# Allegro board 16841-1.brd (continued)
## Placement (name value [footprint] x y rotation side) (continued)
PG5201  GAP-CLOSE-PWR-3-GP  [GAP-CLOSE-PWR-3]  106.19 8.72 90 bottom
PG5204  GAP-CLOSE-PWR-3-GP  [GAP-CLOSE-PWR-3]  106.95 8.72 90 bottom
PG5206  GAP-CLOSE-PWR-3-GP  [GAP-CLOSE-PWR-3]  107.72 8.72 90 bottom
PG5207  GAP-CLOSE-PWR-3-GP  [GAP-CLOSE-PWR-3]  109.24 8.72 90 bottom
PG5208  GAP-CLOSE-PWR-3-GP  [GAP-CLOSE-PWR-3]  108.48 8.72 90 bottom
PG5209  GAP-CLOSE-PWR-3-GP  [GAP-CLOSE-PWR-3]  110 8.72 90 bottom
PG5210  GAP-CLOSE-PWR-3-GP  [GAP-CLOSE-PWR-3]  124.61 5.42 180 bottom
PG5211  GAP-CLOSE-PWR-3-GP  [GAP-CLOSE-PWR-3]  110.76 8.72 90 bottom
PG5212  GAP-CLOSE-PWR-3-GP  [GAP-CLOSE-PWR-3]  124.61 6.18 180 bottom
PG5213  GAP-CLOSE-PWR-3-GP  [GAP-CLOSE-PWR-3]  75.33 1.99 180 top
PG5214  GAP-CLOSE-PWR-3-GP  [GAP-CLOSE-PWR-3]  124.1 4.41 90 bottom
PG5215  GAP-CLOSE-PWR-3-GP  [GAP-CLOSE-PWR-3]  75.33 2.75 180 top
PG5216  GAP-CLOSE-PWR-3-GP  [GAP-CLOSE-PWR-3]  75.33 3.52 180 top
PG5223  GAP-CLOSE-PWR-3-GP  [GAP-CLOSE-PWR-3]  104.77 8.88 0 bottom
PG5405  GAP-CLOSE-PWR-3-GP  [GAP-CLOSE-PWR-3]  39.9 13.8 90 bottom
PG5406  GAP-CLOSE-PWR-3-GP  [GAP-CLOSE-PWR-3]  38.37 13.8 90 bottom
PG5407  GAP-CLOSE-PWR-3-GP  [GAP-CLOSE-PWR-3]  39.14 13.8 90 bottom
PG5408  GAP-CLOSE-PWR-3-GP  [GAP-CLOSE-PWR-3]  44.6 14.31 90 bottom
PG5409  GAP-CLOSE-PWR-3-GP  [GAP-CLOSE-PWR-3]  45.36 14.31 90 bottom
PG5801  GAP-CLOSE-PWR-3-GP  [GAP-CLOSE-PWR-3]  17.8 54.95 90 bottom
PG5802  GAP-CLOSE-PWR-3-GP  [GAP-CLOSE-PWR-3]  20.98 65.24 0 bottom
PG5803  GAP-CLOSE-PWR-3-GP  [GAP-CLOSE-PWR-3]  17.04 54.95 90 bottom
PG8301  GAP-CLOSE-PWR-3-GP  [GAP-CLOSE-PWR-3]  161.95 125.31 0 bottom
PG8302  GAP-CLOSE-PWR-3-GP  [GAP-CLOSE-PWR-3]  161.95 124.55 0 bottom
PG8303  GAP-CLOSE-PWR-3-GP  [GAP-CLOSE-PWR-3]  161.95 123.79 0 bottom
PG8304  GAP-CLOSE-PWR-3-GP  [GAP-CLOSE-PWR-3]  146.07 122.26 90 bottom
PG8305  GAP-CLOSE-PWR-3-GP  [GAP-CLOSE-PWR-3]  145.31 122.26 90 bottom
PG8306  GAP-CLOSE-PWR-3-GP  [GAP-CLOSE-PWR-3]  144.55 122.26 90 bottom
PG8307  GAP-CLOSE-PWR-3-GP  [GAP-CLOSE-PWR-3]  143.78 122.26 90 bottom
PG8308  GAP-CLOSE-PWR-3-GP  [GAP-CLOSE-PWR-3]  190.27 94.96 90 bottom
PG8309  GAP-CLOSE-PWR-3-GP  [GAP-CLOSE-PWR-3]  190.27 94.96 90 top
PG8310  GAP-CLOSE-PWR-3-GP  [GAP-CLOSE-PWR-3]  191.03 94.96 90 top
PG8311  GAP-CLOSE-PWR-3-GP  [GAP-CLOSE-PWR-3]  191.79 94.96 90 top
PG8312  GAP-CLOSE-PWR-3-GP  [GAP-CLOSE-PWR-3]  192.55 94.96 90 top
PG8313  GAP-CLOSE-PWR-3-GP  [GAP-CLOSE-PWR-3]  189 93.69 180 bottom
PG8314  GAP-CLOSE-PWR-3-GP  [GAP-CLOSE-PWR-3]  196.13 75.78 90 bottom
PG8315  GAP-CLOSE-PWR-3-GP  [GAP-CLOSE-PWR-3]  195.37 75.78 90 bottom
PG8316  GAP-CLOSE-PWR-3-GP  [GAP-CLOSE-PWR-3]  194.61 75.78 90 bottom
PG8317  GAP-CLOSE-PWR-3-GP  [GAP-CLOSE-PWR-3]  193.85 75.78 90 bottom
PG8318  GAP-CLOSE-PWR-3-GP  [GAP-CLOSE-PWR-3]  191.03 94.96 90 bottom
PG8319  GAP-CLOSE-PWR-3-GP  [GAP-CLOSE-PWR-3]  191.79 94.96 90 bottom
PG8320  GAP-CLOSE-PWR-3-GP  [GAP-CLOSE-PWR-3]  192.55 94.96 90 bottom
PL4401  COIL-2D2UH-11-GP  [L11510030H158]  175.79 37.81 180 bottom
PL4501  COIL-1D5UH-43-GP  [L4947-1015H119]  190.27 52.03 180 bottom
PL4502  COIL-1UH-34-GP-U1  [L7066-1830-UH119]  199.41 63.21 0 bottom
PL4701  COIL-D15UH-2-GP  [L7366-1930H158]  154.07 62.42 90 bottom
PL4801  COIL-D15UH-2-GP  [L7366-1930H158]  154.33 40.6 90 bottom
PL4802  COIL-D15UH-2-GP  [L7366-1930H158]  154.33 48.6 90 bottom
PL5001  IND-D47UH-22-GP-U  [L7066-1830-UH119]  154.58 31.71 90 bottom
PL5101  COIL-1UH-73-GP  [L4947-1115H119]  38.25 100.8 90 bottom
PL5201  COIL-1UH-34-GP-U1  [L7066-1830-UH119]  110.52 4.43 90 bottom
PL8201  IND-D36UH-42-GP  [L6965-1530H158]  129.43 100.42 180 bottom
PL8202  IND-D36UH-42-GP  [L6965-1530H158]  138.07 100.42 180 bottom
PL8301  IND-1UH-382-GP  [L2520-D620H48]  149.75 123.66 90 bottom
PL8302  IND-D68UH-40-GP  [L4947-1015H119]  191.79 86.7 0 bottom
PQ4301  DMN5L06K-7-GP  [SOT23DGS2D4H48]  60.22 96.86 0 bottom
PQ4302  MMBT3904-5-GP-U  [SOT23CBE2D4H46-U]  60.85 100.54 0 bottom
PQ4304  LMUN5212T1G-GP  [SOT323CBE2D2H40]  14.12 88.45 180 bottom
PQ4305  LTA024EUB-FS8-GP  [SC70-2D2-312H44]  16.66 88.23 0 bottom
PQ4306  2N7002K-1-GP  [SOT23DGS2D4H44]  44.09 76.8 90 top
PQ4307  2N7002KDW-GP  [SOT-363H44]  39.64 78.7 180 top
PQ4308  2N7002KDW-GP  [SOT-363H44]  33.17 78.19 0 top
PQ4309  2N7002KDW-GP  [SOT-363H44]  36.85 74.76 270 top
PQ4310  2N7002KDW-GP  [SOT-363H44]  40.79 83.02 0 top
PQ4311  2N7002KDW-GP  [SOT-363H44]  36.85 77.81 0 top
PQ4312  2N7002K-1-GP  [SOT23DGS2D4H44]  42.69 80.35 90 top
PQ4313  2N7002KDW-GP  [SOT-363H44]  41.55 75.14 0 top
PQ4314  DMN5L06K-7-GP  [SOT23DGS2D4H48]  53.36 93.43 90 bottom
PQ4402  2N7002K-1-GP  [SOT23DGS2D4H44]  139.72 81.49 180 bottom
PQ4405  2N7002KDW-GP  [SOT-363H44]  193.7 70.19 0 top
PQ4408  MMBT3906-4-GP  [SOT23CBE2D4H44]  193.7 65.37 0 top
PQ4415  2N7002KDW-GP  [SOT-363H44]  208.81 28.15 270 bottom
PQ4416  2N7002KDW-GP  [SOT-363H44]  139.21 78.19 180 bottom
PQ8301  2N7002KDW-GP  [SOT-363H44]  124.48 123.53 270 bottom
PQ8305  2N7002KDW-GP  [SOT-363H44]  124.49 117.94 270 bottom
PQ8306  2N7002KDW-GP  [SOT-363H44]  124.48 115.28 270 bottom
PQ8307  2N7002KDW-GP  [SOT-363H44]  124.48 120.99 270 bottom
PQ8308  2N7002KDW-GP  [SOT-363H44]  203.98 64.35 180 top
PR4302  15KR2F-GP  [R402H16]  57.55 101.81 180 bottom
PR4303  10KR2J-3-GP  [R402H16]  63.01 100.54 180 bottom
PR4304  2K2R2J-2-GP  [R402H16]  55.27 95.46 270 bottom
PR4305  33R2J-2-GP  [R402H16]  62.38 98 0 bottom
PR4306  33R2J-2-GP  [R402H16]  62.38 96.23 0 bottom
PR4307  240KR3-GP  [R603H22]  18.18 88.1 0 top
PR4308  47KR2F-GP  [R402H16]  19.45 86.07 0 top
PR4309  100KR2J-1-GP  [R402H16]  58.31 101.81 0 bottom
PR4310  1KR2J-1-GP  [R402H16]  39.64 74.89 0 top
PR4311  100KR2F-L1-GP  [R402H16]  18.94 79.18 270 top
PR4312  470KR2F-GP  [R402H16]  15.77 86.46 180 bottom
PR4313  84K5R2F-GP  [R402H16]  17.04 86.07 270 bottom
PR4315  18K7R2F-GP  [R402H16]  17.04 79.08 0 top
PR4316  20KR2J-L2-GP  [R402H16]  18.94 79.97 270 top
PR4317  -  [0R0603-PAD]  22.37 96.61 180 top
PR4318  100KR2J-1-GP  [R402H16]  24.79 81.62 180 top
PR4319  200KR2F-L-GP  [R402H16]  41.55 77.05 270 top
PR4320  240KR2F-L-GP  [R402H16]  24.81 78.29 0 top
PR4321  47KR2F-GP  [R402H16]  27.66 77.48 90 top
PR4322  10KR2F-2-GP  [R402H16]  27.71 87.08 0 top
PR4323  100KR2F-L1-GP  [R402H16]  44.72 79.84 180 top
PR4324  100KR2F-L1-GP  [R402H16]  38.88 74.89 180 top
PR4327  10KR2F-2-GP  [R402H16]  31.97 80.22 270 top
PR4328  20KR2F-L-GP  [R402H16]  33.68 80.22 270 top
PR4330  240KR2F-L-GP  [R402H16]  35.45 91.22 90 top
PR4332  100KR2F-L1-GP  [R402H16]  40.15 81.11 270 top
PR4333  10KR2F-2-GP  [R402H16]  24.79 83.4 0 top
PR4335  10KR2J-3-GP  [R402H16]  17.04 81.62 270 bottom
PR4336  680KR2J-GP  [R402H16]  29.05 87.26 90 top
PR4337  240KR2F-L-GP  [R402H16]  35.58 79.84 270 top
PR4338  100R2512J-1-GP  [R2512H28]  35.83 84.29 90 top
PR4339  64K9R2F-1-GP  [R402H16]  35.07 73.37 90 top
PR4340  100KR2F-L1-GP  [R402H16]  34.56 74.64 270 top
PR4341  -  [0R0402-PAD]  34.95 76.16 90 top
PR4342  100KR2F-L1-GP  [R402H16]  35.58 80.61 90 top
PR4343  200KR2F-L-GP  [R402H16]  43.58 73.87 270 top
PR4344  680KR2J-GP  [R402H16]  39.77 72.35 270 top
PR4345  100KR2J-1-GP  [R402H16]  47.9 94.19 0 bottom
PR4346  137KR2F-1-GP  [R402H16]  46.5 92.16 270 bottom
PR4347  100KR2F-L1-GP  [R402H16]  47.39 92.92 270 bottom
PR4401  D02R6F-GP  [R1206H24]  193.19 41.24 90 bottom
PR4402  2D2R3-1-U-GP  [R603H22]  199.16 35.39 180 bottom
PR4403  2D2R5J-1-GP  [R805H24]  205.51 31.84 270 bottom
PR4404  402KR2F-GP  [R402H16]  213.89 28.79 0 bottom
PR4405  4D7R2F-GP  [R402H16]  194.97 32.98 90 bottom
PR4406  100KR2F-L1-GP  [R402H16]  208.17 30.44 0 bottom
PR4407  D01R3721F-GP-U  [R3720H40]  180.49 27.01 90 bottom
PR4408  2D2R3-1-U-GP  [R603H22]  194.71 29.42 270 bottom
PR4409  100KR2F-L1-GP  [R402H16]  200.55 23.46 180 bottom
PR4410  105KR2F-1-GP  [R402H16]  199.03 23.46 0 bottom
PR4411  499R2F-2-GP  [R402H16]  197.51 22.69 180 bottom
PR4412  -  [0R0402-PAD]  196.74 22.69 180 bottom
PR4413  6K04R2F-GP  [R402H16]  195.98 22.69 180 bottom
PR4414  -  [0R0805-PAD]  183.41 43.39 90 top
PR4416  2D2R5J-1-GP  [R805H24]  180.74 40.85 90 top
PR4417  100KR2F-L1-GP  [R402H16]  202.33 29.81 90 top
PR4420  -  [0R0805-PAD]  183.28 31.71 270 top
PR4422  3D3R2F-GP  [R402H16]  202.33 36.28 180 bottom
PR4423  3D3R2F-GP  [R402H16]  201.57 36.28 180 bottom
PR4424  1R2F-L-GP  [R402H16]  194.84 27.01 270 bottom
PR4425  1R2F-L-GP  [R402H16]  194.84 26.25 270 bottom
PR4426  196KR2F-GP  [R402H16]  205.13 26.5 270 bottom
PR4427  100KR2F-L2-GP  [R402H16]  208.81 26.4 270 bottom
PR4429  100KR2F-L2-GP  [R402H16]  205.13 27.27 90 bottom
PR4435  100KR2F-L3-GP  [R402H16]  140.86 76.16 180 bottom
PR4436  1MR2J-1-GP  [R402H16]  193.31 63.33 270 top
PR4450  10KR2F-2-GP  [R402H16]  190.65 71.59 180 top
PR4462  -  [0R0402-PAD]  193.7 67.91 0 top
PR4463  0R2J-2-GP  [R402H16]  194.46 67.91 0 top
PR4472  100KR2F-L3-GP  [R402H16]  140.86 78.07 0 bottom
PR4473  100KR2J-1-GP  [R402H16]  194.71 62.83 180 top
PR4474  100KR2F-L1-GP  [R402H16]  193.95 72.1 270 top
PR4475  680KR2F-GP  [R402H16]  192.37 66.53 270 top
PR4476  -  [0R0402-PAD]  138.58 75.78 0 bottom
PR4477  -  [0R0402-PAD]  187.22 64.6 90 top
PR4478  100R2F-L1-GP-U  [R402H14]  193.06 23.96 90 bottom
PR4501  -  [0R0603-PAD]  186.2 53.94 180 bottom
PR4502  -  [0R0603-PAD]  194.08 66.25 180 bottom
PR4503  0R2J-2-GP  [R402H16]  192.3 60.79 0 top
PR4504  -  [0R0402-PAD]  200.81 70.95 0 top
PR4505  100KR2J-1-GP  [R402H16]  191.79 60.92 180 bottom
PR4506  1KR2F-3-GP  [R402H16]  194.71 56.22 270 bottom
PR4507  1KR2F-3-GP  [R402H16]  200.93 70.95 180 bottom
PR4508  200KR2F-L1-GP  [R402H16]  194.46 60.29 270 bottom
PR4509  1KR2F-3-GP  [R402H16]  194.89 62.85 180 bottom
PR4510  100KR2J-1-GP  [R402H16]  197.81 73.16 0 bottom
PR4511  1KR2F-3-GP  [R402H16]  199.28 72.6 0 top
PR4512  200KR2F-L1-GP  [R402H16]  198.52 72.6 180 top
PR4513  1MR2J-1-GP  [R402H16]  200.05 70.95 180 top
PR4514  1MR2J-1-GP  [R402H16]  192.04 58 270 top
PR4515  -  [0R0402-PAD]  193.19 60.79 180 top
PR4516  -  [0R0402-PAD]  192.04 58.76 90 top
PR4530  0R2J-2-GP  [R402H16]  191.54 60.79 180 top
PR4551  348KR2F-GP  [R402H16]  200.22 73.27 270 bottom
PR4601  0R0402-PAD-1-GP  [0R0402-PAD]  182.27 70.83 270 bottom
PR4602  0R0402-PAD-1-GP  [0R0402-PAD]  182.27 70.06 270 bottom
PR4603  1KR2F-3-GP  [R402H16]  184.55 60.41 90 top
PR4604  100R2F-L3-GP  [R402H16]  184.55 62.7 90 top
PR4605  75R2F-2-GP  [R402H16]  184.55 61.94 90 top
PR4606  45D3R2F-L-GP  [R402H16]  184.55 61.17 90 top
PR4607  100R2F-L3-GP  [R402H16]  184.82 60.43 90 bottom
PR4608  90K9R2F-GP  [R402H16]  180.23 60.54 0 top
PR4609  10KR2F-L1-GP  [R402H15]  184.82 59.67 90 bottom
PR4610  1R2J-GP  [R402H16]  182.27 61.56 180 top
PR4611  NTC-10K-26-GP-U  [NTC-402H22-U]  154.71 35.65 90 bottom
PR4612  0R0402-PAD-1-GP  [0R0402-PAD]  184.42 65.75 270 top
PR4613  0R0402-PAD-1-GP  [0R0402-PAD]  184.04 66 270 bottom
PR4614  0R2J-L-GP  [R402H15]  181 60.54 180 top
PR4615  1KR2F-3-GP  [R402H16]  181.38 65.11 0 top
PR4616  10KR2F-L1-GP  [R402H15]  182.27 58.89 270 bottom
PR4617  NTC-470K-8-GP-U  [NTC-402H22-U]  159.28 43.52 180 bottom
PR4618  11KR2F-L-GP  [R402H16]  182.01 67.02 180 bottom
PR4620  392R2F-GP  [R402H16]  180.11 65.49 270 top
PR4621  27K4R2F-GP  [R402H16]  184.04 58.13 90 bottom
PR4622  10R2F-L1-GP  [R402H16]  184.44 62.72 90 bottom
PR4623  0R0402-PAD-1-GP  [0R0402-PAD]  184.44 61.95 90 bottom
PR4624  49D9R2F-L1-GP  [R402H16]  184.82 61.19 90 bottom
PR4625  2K61R2F-1-GP  [R402H16]  184.04 67.52 270 bottom
PR4626  3K3R2F-2-GP  [R402H16]  182.27 58.13 90 bottom
PR4627  100R2F-L1-GP-U  [R402H14]  181.5 69.18 90 bottom
PR4628  9K31R2F-GP  [R402H16]  184.17 64.48 270 bottom
PR4629  88K7R2F-GP  [R402H16]  184.17 63.71 270 bottom
PR4630  2KR2F-L1-GP  [R402H16]  181.96 56.91 0 bottom
PR4631  100R2F-L1-GP-U  [R402H14]  183.41 53.55 180 bottom
PR4632  301R2F-GP  [R402H16]  178.71 68.79 180 bottom
PR4633  3K01R2F-3-GP  [R402H16]  180.44 56.91 0 bottom
PR4635  1KR2F-3-GP  [R402H16]  171.34 55.08 0 bottom
PR4636  499R2F-2-GP  [R402H16]  181.2 56.91 0 bottom
PR4637  1K69R2F-2-GP  [R402H16]  180.23 68.79 0 bottom
PR4638  2KR2F-L1-GP  [R402H16]  179.47 68.79 180 bottom
PR4639  100R2F-L1-GP-U  [R402H14]  178.2 58.63 90 top
PR4640  2K49R2F-2-L-GP  [R402H16]  176.17 69.18 90 bottom
PR4641  2K61R2F-1-GP  [R402H16]  171.98 51.52 90 bottom
PR4642  324R2F-GP  [R402H16]  176.17 57.36 180 bottom
PR4643  11KR2F-L-GP  [R402H16]  178.07 56.09 90 bottom
PR4644  113KR2F-1-GP  [R402H16]  176.17 66.89 90 bottom
PR4645  1KR2F-L1-GP  [R402H15]  175.41 57.36 180 bottom
PR4646  NTC-10K-26-GP-U  [NTC-402H22-U]  156.61 44.54 270 bottom
PR4647  0R0402-PAD-1-GP  [0R0402-PAD]  176.3 55.08 180 bottom
PR4648  274R2F-GP  [R402H16]  173.01 66.91 90 bottom
PR4649  0R0402-PAD-1-GP  [0R0402-PAD]  169.31 66.25 0 bottom
PR4650  NTC-10K-26-GP-U  [NTC-402H22-U]  154.71 66.51 90 bottom
PR4651  1KR2F-L1-GP  [R402H15]  171.72 67.4 180 bottom
PR4652  11KR2F-L-GP  [R402H16]  171.72 65.62 0 bottom
PR4653  2K61R2F-1-GP  [R402H16]  173.38 64.86 180 bottom
PR4654  NTC-470K-8-GP-U  [NTC-402H22-U]  153.56 53.3 180 bottom
PR4655  27K4R2F-GP  [R402H16]  168.95 58.65 270 bottom
PR4656  2K87R2F-1-GP  [R402H16]  171.74 59.41 90 bottom
PR4657  2KR2F-L1-GP  [R402H16]  171.72 61.05 90 bottom
PR4658  499R2F-2-GP  [R402H16]  171.75 62.57 90 bottom
PR4659  100R2F-L1-GP-U  [R402H14]  171.22 63.84 180 bottom
PR4660  1K91R2F-1-GP  [R402H16]  171.72 61.81 90 bottom
PR4661  86K6R2F-GP  [R402H16]  171.74 57.13 90 bottom
PR4662  10KR2F-L1-GP  [R402H15]  171.74 58.65 90 bottom
PR4663  100R2F-L1-GP-U  [R402H14]  168.8 61.43 0 bottom
PR4665  0R0402-PAD-1-GP  [0R0402-PAD]  180.74 53.43 0 bottom
PR4666  0R0402-PAD-1-GP  [0R0402-PAD]  179.85 53.81 0 bottom
PR4667  0R0402-PAD-1-GP  [0R0402-PAD]  168.04 63.08 180 bottom
PR4668  0R0402-PAD-1-GP  [0R0402-PAD]  169.31 64.22 270 bottom
PR4669  0R2J-L-GP  [R402H15]  174.01 57.87 270 bottom
PR4670  267R2F-1-GP  [R402H16]  176.93 57.36 180 bottom
PR4671  1K54R2F-GP  [R402H16]  179.67 56.91 0 bottom
PR4672  88K7R2F-GP  [R402H16]  179.47 59.07 180 top
PR4701  0R0402-PAD-1-GP  [0R0402-PAD]  168.55 66.25 0 bottom
PR4702  0R0402-PAD-1-GP  [0R0402-PAD]  151.91 55.46 0 bottom
PR4703  2D2R6J-3-GP  [R1206H28]  153.82 59.14 270 top
PR4704  2D2R2F-GP  [R402H16]  151.79 58 180 bottom
PR4705  2D2R3F-L-GP  [R603H24]  154.58 53.4 0 bottom
PR4706  0R0402-PAD-1-GP  [0R0402-PAD]  153.31 58 180 bottom
PR4708  3K65R2F-1-GP  [R402H16]  168.93 64.98 270 bottom
PR4712  5K11R2F-L1-GP  [R402H16]  152.67 55.46 0 bottom
PR4802  0R0402-PAD-1-GP  [0R0402-PAD]  163.22 36.16 270 bottom
PR4803  2D2R2F-GP  [R402H16]  156.74 36.16 180 bottom
PR4804  2D2R3-1-U-GP  [R603H22]  165.76 37.43 90 bottom
PR4805  2D2R6J-3-GP  [R1206H28]  158.01 40.85 90 top
PR4806  0R0402-PAD-1-GP  [0R0402-PAD]  160.68 36.79 270 bottom
PR4808  3K65R2F-1-GP  [R402H16]  171.72 53.05 90 bottom
PR4809  10R2F-L1-GP  [R402H16]  173.5 56.35 270 bottom
PR4810  2D2R3-1-U-GP  [R603H22]  165.5 45.55 90 bottom
PR4811  0R0402-PAD-1-GP  [0R0402-PAD]  162.71 45.17 270 top
PR4812  0R0402-PAD-1-GP  [0R0402-PAD]  159.79 45.17 270 bottom
PR4813  2D2R2F-GP  [R402H16]  159.79 45.17 270 top
PR4814  2D2R6J-3-GP  [R1206H28]  157.88 48.73 90 top
PR4815  10R2F-L1-GP  [R402H16]  174.77 55.21 0 bottom
PR4816  3K65R2F-1-GP  [R402H16]  171.98 52.28 90 bottom
PR4817  5K11R2F-L1-GP  [R402H16]  163.22 36.92 270 bottom
PR4818  5K11R2F-L1-GP  [R402H16]  163.09 45.17 270 bottom
PR4821  100KR2F-L1-GP  [R402H16]  171.85 53.81 90 bottom
PR4822  100KR2F-L1-GP  [R402H16]  172.61 55.59 90 bottom
PR4823  100KR2F-L1-GP  [R402H16]  171.72 56.35 90 bottom
PR4824  100KR2F-L1-GP  [R402H16]  174.26 53.94 90 bottom
PR5001  2D2R3F-L-GP  [R603H24]  171.6 30.19 180 bottom
PR5003  3K65R2F-1-GP  [R402H16]  181.76 67.14 270 top
PR5004  0R0402-PAD-1-GP  [0R0402-PAD]  181.76 66.38 270 top
PR5101  20KR2F-L-GP  [R402H16]  43.2 95.97 180 bottom
PR5102  0R0603-PAD-1-GP-U  [0R0603-PAD-U]  41.93 102.58 270 top
PR5103  0R2J-2-GP  [R402H16]  41.68 98.26 270 top
PR5104  100KR2J-1-GP  [R402H16]  45.49 97.75 90 top
PR5105  1MR2J-1-GP  [R402H16]  45.49 96.1 180 bottom
PR5106  0R2J-2-GP  [R402H16]  43.33 98.77 0 top
PR5107  20KR2F-L-GP  [R402H16]  44.72 96.1 0 bottom
PR5114  -  [0R0402-PAD]  60.85 12.28 90 bottom
PR5118  -  [0R0402-PAD]  60.85 10.76 270 bottom
PR5125  -  [0R0402-PAD]  60.85 14.57 90 bottom
PR5126  0R2J-2-GP  [R402H16]  60.85 15.33 90 bottom
PR5201  88K7R2F-GP  [R402H16]  119.91 7.45 270 top
PR5202  2K55R2F-GP  [R402H16]  118.89 9.61 270 bottom
PR5203  100KR2F-L1-GP  [R402H16]  118.13 7.45 90 top
PR5204  10KR2F-2-GP  [R402H16]  118.89 8.85 90 bottom
PR5208  100KR2J-1-GP  [R402H16]  117.24 8.98 270 top
PR5209  -  [0R0402-PAD]  117.24 9.74 270 top
PR5210  -  [0R0402-PAD]  117.22 9.74 270 bottom
PR5401  47KR2J-2-GP  [R402H16]  36.22 2.63 180 bottom
PR5402  100KR2F-L1-GP  [R402H16]  39.14 3.01 90 bottom
PR5403  16K5R2F-2-GP  [R402H16]  38.88 11.77 90 bottom
PR5404  13K3R2F-L1-GP  [R402H16]  37.1 11.52 90 bottom
PR5406  -  [0R0402-PAD]  36.98 2.63 0 bottom
PR5408  -  [0R0402-PAD]  37.74 3.01 0 bottom
PR5409  47KR2J-2-GP  [R402H16]  42.44 2.63 180 bottom
PR5410  10KR2F-2-GP  [R402H16]  44.6 3.14 90 bottom
PR5417  -  [0R0402-PAD]  44.39 1.89 0 bottom
PR5419  29K4R2F-GP  [R402H16]  44.22 12.28 90 bottom
PR5420  13K7R2F-GP  [R402H16]  43.66 14.69 0 bottom
PR8201  499KR2F-1-GP  [R402H16]  135.4 123.91 180 bottom
PR8202  2D2R2F-GP  [R402H16]  137.38 124.29 90 bottom
PR8203  100KR2J-1-GP  [R402H16]  138.96 120.48 90 bottom
PR8206  20KR2F-L-GP  [R402H16]  134.64 123.91 0 bottom
PR8207  -  [0R0402-PAD]  131.59 123.91 180 bottom
PR8208  2KR2F-3-GP  [R402H16]  133.88 123.91 0 bottom
PR8209  18KR2F-GP  [R402H16]  133.88 123.91 180 top
PR8210  -  [0R0603-PAD]  130.46 118.28 90 bottom
PR8211  -  [0R0603-PAD]  139.47 118.58 270 bottom
PR8212  100R2F-L1-GP-U  [R402H14]  139.47 121.88 0 bottom
PR8213  100R2F-L1-GP-U  [R402H14]  139.47 123.66 0 bottom
PR8215  2D2R5F-2-GP  [R805H24]  134.92 102.98 180 top
PR8216  2D2R5F-2-GP  [R805H24]  133.12 102.98 180 top
PR8220  -  [0R0402-PAD]  140.74 123.15 270 bottom
PR8221  -  [0R0402-PAD]  140.74 122.39 270 bottom
PR8222  20KR2F-L-GP  [R402H16]  133.12 123.91 0 bottom
PR8223  2D2R3J-2-GP  [R603H22]  134.03 116.04 180 top
PR8224  8K45R2F-2-GP  [R402H16]  132.91 115.78 180 bottom
PR8256  1KR2J-1-GP  [R402H16]  128.04 120.1 180 bottom
PR8257  -  [0R0402-PAD]  130.2 122.19 90 top
PR8258  10KR2J-3-GP  [R402H16]  130.2 121.42 90 top
PR8259  10KR2J-3-GP  [R402H16]  130.2 122.96 270 top
PR8260  13KR2F-GP  [R402H16]  126.51 119.47 270 bottom
PR8301  2D2R2F-GP  [R402H16]  157.63 122.64 0 bottom
PR8302  51KR2F-L-GP  [R402H16]  156.1 125.18 90 bottom
PR8303  38K3R2F-GP  [R402H16]  158.14 124.29 90 bottom
PR8304  100KR2F-L1-GP  [R402H16]  153.21 124.75 0 top
PR8306  100R2J-2-GP  [R402H14]  126.77 122.77 90 bottom
PR8307  100KR2J-1-GP  [R402H16]  122.58 123.43 0 bottom
PR8308  -  [0R0402-PAD]  152.55 125.18 270 bottom
PR8309  100R2J-2-GP  [R402H14]  126.77 117.44 90 bottom
PR8310  1KR2J-1-GP  [R402H16]  126.77 124.29 90 bottom
PR8311  100KR2F-L1-GP  [R402H16]  190.9 75.91 0 bottom
PR8313  18KR2F-GP  [R402H16]  159.66 124.17 90 top
PR8315  100KR2J-1-GP  [R402H16]  122.58 117.97 180 bottom
PR8316  100R2J-2-GP  [R402H14]  129.94 119.72 90 bottom
PR8317  100KR2J-1-GP  [R402H16]  122.58 115.28 180 bottom
PR8318  100R2J-2-GP  [R402H14]  126.77 120.23 90 bottom
PR8319  100KR2J-1-GP  [R402H16]  122.58 120.74 180 bottom
PR8320  -  [0R0402-PAD]  153.97 124.75 180 top
PR8321  -  [0R0402-PAD]  191.66 75.91 0 bottom
PR8322  -  [0R0402-PAD]  190.14 75.91 0 bottom
PR8323  0R2J-2-GP  [R402H16]  188.62 75.91 0 bottom
PR8324  -  [0R0603-PAD]  195.85 82.51 0 bottom
PR8325  -  [0R0402-PAD]  188.74 80.35 90 bottom
PR8326  12KR2F-L-GP  [R402H16]  187.47 79.46 90 bottom
PR8327  15KR2F-GP  [R402H16]  187.47 77.94 270 bottom
PR8328  100KR2J-1-GP  [R402H16]  205.89 63.08 90 top
PR8329  100R2J-2-GP  [R402H14]  199.28 74.51 90 top
PR8330  -  [0R0402-PAD]  126.77 120.99 270 bottom
PR8331  -  [0R0402-PAD]  126.77 114.9 270 bottom
PT4402  SE33U25VM-11-GP  [CT7343H83]  184.17 48.6 0 bottom
PT4701  SE330U2VDM-4-GP  [CT7343H83]  147.34 59.02 180 bottom
PT4801  SE330U2VDM-4-GP  [CT7343H83]  147.59 41.87 180 bottom
PT4803  SE330U2VDM-4-GP  [CT7343H83]  147.34 50.89 0 bottom
PT4805  SE33U25VM-11-GP  [CT7343H83]  189.25 65.62 270 bottom
PT8206  SE330U2VDM-4-GP  [CT7343H83]  127.78 93.94 90 bottom
PT8207  SE330U2VDM-4-GP  [CT7343H83]  140.36 87.46 180 bottom
PT8208  SE330U2VDM-4-GP  [CT7343H83]  137.94 93.94 270 bottom
PU4301  AON7403-GP-U  [PPAK-8P-3232H36]  21.99 84.42 180 top
PU4302  AON7403-GP-U  [PPAK-8P-3232H36]  21.36 80.1 90 top
PU4303  AON7403-GP-U  [PPAK-8P-3232H36]  30.07 83.2 180 top
PU4304  AON7403-GP-U  [PPAK-8P-3232H36]  29.61 79.84 270 top
PU4305  SI7625DN-T1-GE3-GP  [PPAK-8P-2H45]  32.53 88.86 90 top
PU4306  SI7625DN-T1-GE3-GP  [PPAK-8P-2H45]  38.37 88.86 270 top
PU4307  SN74AUP1G04DRYR-GP  [XSON6H24]  44.47 50.89 270 top
PU4401  ISL9538HRTZ-GP-U  [QFN32J4-G2D85H34]  200.05 29.55 270 bottom
PU4403  AON7380-GP  [PPAK-8P-3232H36]  183.66 42.63 90 bottom
PU4404  AON7380-GP  [PPAK-8P-3232H36]  182.39 38.82 270 bottom
PU4405  AON7380-GP  [PPAK-8P-3232H36]  183.66 31.2 90 bottom
PU4406  AON7380-GP  [PPAK-8P-3232H36]  182.39 35.01 270 bottom
PU4412  AON7401-GP  [PPAK-8P-3232H36]  173.38 26.38 270 bottom
PU4501  SY8286BRAC-GP  [QFN20Z3-G1D1H36]  191.03 57.24 270 bottom
PU4502  SY8288CRAC-GP  [QFN20Z3-G1D1H36]  196.11 70.19 270 bottom
PU4601  ISL95859AHRTZ-T-GP  [QFN40J5-G3D6-DIFF-H34]  178.71 62.44 0 bottom
PU4701  CSD97396Q4M-GP  [DFN8J4535-G4122-U1H40]  156.36 56.73 180 bottom
PU4801  CSD97396Q4M-GP  [DFN8J4535-G4122-U1H40]  161.06 39.84 270 bottom
PU4802  CSD97396Q4M-GP  [DFN8J4535-G4122-U1H40]  161.06 48.09 270 bottom
PU5001  ISL95808HRZ-T-1-GP  [DFN8G2-G1710-U1H40]  168.93 29.68 90 bottom
PU5002  AON7410-GP  [PPAK-8P-3232H36]  161.44 33.74 90 bottom
PU5003  AON7410-GP  [PPAK-8P-3232H36]  160.17 29.93 270 bottom
PU5101  SY8288RAC-GP  [QFN20Z3-G1H36]  44.34 100.16 180 bottom
PU5102  APL5338XAI-TRG-GP  [MSOP10-G2D5H44]  56.15 12.91 90 bottom
PU5201  AOZ2262QI-10-GP-U  [QFN22G4-G2PH42]  118.13 5.55 180 bottom
PU5401  APL5930KAI-TRG-GP  [SOIC8-G3530H63]  38.63 7.71 0 bottom
PU5403  APL5930KAI-TRG-GP  [SOIC8-G3530H63]  44.09 7.71 0 bottom
PU8201  RT8812AGQW-GP  [QFN20-G1D75H32]  134.78 119.8 270 bottom
PU8202  FDMS3600-02-RJK0215-COLAY-GP  [PPAK-8P-G5324H44-COLAY]  128.8 108.67 90 bottom
PU8204  FDMS3600-02-RJK0215-COLAY-GP  [PPAK-8P-G5324H44-COLAY]  128.8 108.67 270 top
PU8206  FDMS3600-02-RJK0215-COLAY-GP  [PPAK-8P-G5324H44-COLAY]  139.34 108.67 90 top
PU8208  FDMS3600-02-RJK0215-COLAY-GP  [PPAK-8P-G5324H44-COLAY]  139.34 108.67 270 bottom
PU8301  RT8068AZQWID-GP-U  [DFN10G3-G265175H32]  155.21 123.02 270 bottom
PU8302  SY8288RAC-GP  [QFN20Z3-G1H36]  192.3 79.97 90 bottom
PWSW1  SW-TACT-4P-59-GP  [TJE-533-S-V-T-R-744]  138.7 16.98 180 bottom
Q501  DMN5L06K-7-GP  [SOT23DGS2D4H48]  85.92 93.46 0 bottom
Q1701  PJT138KA-GP  [SOT-363H44]  89.81 13.8 90 top
Q1702  2N7002KDW-GP  [SOT-363H44]  87.14 16.22 90 top
Q1801  2N7002KDW-GP  [SOT-363H44]  68.73 15.45 0 top
Q1802  2N7002K-1-GP  [SOT23DGS2D4H44]  75.2 24.34 180 top
Q2001  PJT138KA-GP  [SOT-363H44]  92.5 32.64 180 top
Q2408  2N7002K-1-GP  [SOT23DGS2D4H44]  140.48 17.36 180 top
Q2414  2N7002K-1-GP  [SOT23DGS2D4H44]  141.63 22.19 90 bottom
Q2416  2N7002KDW-GP  [SOT-363H44]  164.49 12.15 270 top
Q2417  2N7002KDW-GP  [SOT-363H44]  142.79 3.59 180 top
Q2505  2N7002K-1-GP  [SOT23DGS2D4H44]  172.74 5.04 270 top
Q2601  2N7002KDW-GP  [SOT-363H44]  56.92 15.96 90 top
Q2602  2N7002K-1-GP  [SOT23DGS2D4H44]  45.11 10.37 90 top
Q2603  MMBT3904-5-GP-U  [SOT23CBE2D4H46-U]  170.71 45.93 270 bottom
Q2701  2N7002K-1-GP  [SOT23DGS2D4H44]  20.09 34 180 top
Q2702  DMP2130L-7-GP  [SOT23DGS2D4H48]  24.91 31.38 270 top
Q3701  2N7002K-1-GP  [SOT23DGS2D4H44]  39.77 29.86 90 top
Q6105  DMN5L06K-7-GP  [SOT23DGS2D4H48]  48.79 6.18 180 bottom
Q6401  RN2418-GP  [SOT23CBE2D6H62]  49.04 9.49 90 bottom
Q6402  RN2418-GP  [SOT23CBE2D6H62]  48.92 2.88 90 bottom
Q6501  PJA3402-R1-00001-GP  [SOT23DGS2D4H44]  92.35 15.58 90 bottom
Q6502  DMP2130L-7-GP  [SOT23DGS2D4H48]  119.65 13.17 180 bottom
Q6503  2N7002K-1-GP  [SOT23DGS2D4H44]  121.43 16.17 90 bottom
Q6504  2N7002KDW-GP  [SOT-363H44]  123.59 18.76 180 bottom
Q6505  RN2418-GP  [SOT23CBE2D6H62]  144.29 25.23 180 bottom
Q7001  2N7002KDW-GP  [SOT-363H44]  214.4 55.71 90 top
Q7301  2N7002K-1-GP  [SOT23DGS2D4H44]  156.74 67.8 0 bottom
Q7601  2N7002KDW-GP  [SOT-363H44]  188.23 69.56 90 top
Q7606  2N7002K-1-GP  [SOT23DGS2D4H44]  187.22 71.97 90 bottom
Q7801  2N7002K-1-GP  [SOT23DGS2D4H44]  190.65 112.99 180 bottom
Q7901  2N7002K-1-GP  [SOT23DGS2D4H44]  144.29 116.17 0 bottom
Q8301  2N7002K-1-GP  [SOT23DGS2D4H44]  120.67 93.43 90 bottom
Q9102  DMP2130L-7-GP  [SOT23DGS2D4H48]  216.17 31.2 180 bottom
Q9104  2N7002K-2-GP  [SOT23DGS2D4H44]  219.73 31.2 180 bottom
R401  1KR2J-1-GP  [R402H16]  136.16 75.78 270 bottom
R402  51R2J-2-GP  [R402H16]  138.32 69.05 180 bottom
R403  499R2F-2-GP  [R402H16]  136.16 75.02 90 bottom
R404  100KR2J-1-GP  [R402H16]  99.97 32.73 90 bottom
R406  51R2J-2-GP  [R402H16]  136.16 70.95 270 bottom
R407  51R2J-2-GP  [R402H16]  125.7 69.3 270 top
R408  51R2J-2-GP  [R402H16]  136.16 67.14 270 bottom
R409  51R2J-2-GP  [R402H16]  136.16 66.38 270 bottom
R410  -  [0R0402-PAD]  98.29 32.73 270 bottom
R412  49D9R2F-GP  [R402H16]  97.81 52.03 270 top
R413  49D9R2F-GP  [R402H16]  97.81 51.27 270 top
R414  49D9R2F-GP  [R402H16]  125.75 73.37 180 top
R415  49D9R2F-GP  [R402H16]  124.99 73.37 180 top
R416  51R2J-2-GP  [R402H16]  136.16 68.67 270 bottom
R417  1KR2J-1-GP  [R402H16]  136.16 67.91 270 bottom
R419  1KR2J-1-GP  [R402H16]  138.45 73.75 90 bottom
R421  51R2J-2-GP  [R402H16]  136.16 69.43 270 bottom
R422  51R2J-2-GP  [R402H16]  136.16 65.62 270 bottom
R423  51R2J-2-GP  [R402H16]  136.16 70.19 270 bottom
R501  121R2F-GP  [R402H16]  97.81 50.51 270 top
R502  80D6R2F-L-GP  [R402H16]  97.81 53.55 270 top
R503  100R2F-L1-GP-U  [R402H14]  97.81 52.79 270 top
R504  -  [0R0402-PAD]  106.57 16.98 180 bottom
R505  470R2F-GP  [R402H16]  104.9 17 0 bottom
R506  220KR2F-GP  [R402H16]  85.41 96 180 bottom
R601  49D9R2F-GP  [R402H16]  126.72 70.06 270 top
R602  -  [0R0402-PAD]  97.81 77.94 270 top
R603  100KR2J-1-GP  [R402H16]  138.45 74.51 270 bottom
R604  1KR2J-1-GP  [R402H16]  124.73 79.84 0 bottom
R605  1KR2J-1-GP  [R402H16]  125.5 79.84 0 bottom
R705  -  [0R0805-PAD]  97.81 55.46 0 top
R709  -  [0R0402-PAD]  138.45 70.7 270 bottom
R719  100R2F-L1-GP-U  [R402H14]  127.5 55.46 0 top
R720  100R2F-L1-GP-U  [R402H14]  126.64 53.43 270 top
R721  100R2F-L1-GP-U  [R402H14]  123.72 77.18 90 top
R722  100R2F-L1-GP-U  [R402H14]  125.62 76.67 0 top
R723  54D9R2F-L1-GP  [R402H16]  138.45 72.22 90 bottom
R726  100R2F-L1-GP-U  [R402H14]  138.45 71.46 90 bottom
R727  56R2J-4-GP  [R402H16]  138.45 72.99 90 bottom
R728  220R2J-L2-GP  [R402H16]  136.16 72.99 90 bottom
R732  -  [0R0402-PAD]  136.16 72.22 270 bottom
R734  100R2F-L1-GP-U  [R402H14]  127.05 46.94 90 top
R735  100R2F-L1-GP-U  [R402H14]  125.6 46.47 0 top
R736  D0002R5J-GP-U  [R805H20]  123.59 59.52 180 top
R738  0R2J-2-GP  [R402H16]  126.13 65.87 0 top
R742  D0002R5J-GP-U  [R805H20]  123.72 63.59 180 top
R743  D0002R5J-GP-U  [R805H20]  115.31 60.16 180 top
R801  24D9R2F-L-GP  [R402H16]  126.26 63.08 180 top
R802  10KR2J-3-GP  [R402H16]  122.45 24.73 180 bottom
R803  100KR2J-1-GP  [R402H16]  125.5 24.73 0 bottom
R804  -  [0R0402-PAD]  124.73 24.73 180 bottom
R1101  -  [0R1206-PAD]  103.78 12.28 270 top
R1102  -  [0R0603-PAD]  123.97 32.85 180 top
R1103  -  [0R0603-PAD]  112.16 35.52 180 top
R1104  -  [0R0603-PAD]  116.71 32.32 270 top
R1204  10KR2F-L1-GP  [R402H15]  65.04 21.55 90 top
R1205  -  [0R0402-PAD]  63.27 21.55 270 top
R1206  2R2F-GP  [R402H16]  70.25 46.95 90 top
R1208  10KR2F-L1-GP  [R402H15]  65.81 20.66 90 top
R1209  24D9R2F-L-GP  [R402H16]  70.25 48.47 90 top
R1210  -  [0R0402-PAD]  64.41 19.39 0 top
R1211  10KR2F-L1-GP  [R402H15]  59.74 43.32 270 top
R1212  -  [0R0402-PAD]  61.46 43.29 90 top
R1215  240R2F-1-GP  [R402H16]  59.84 52.41 270 top
R1216  SC2D2U10V3KX-L-GP  [C603H36]  66.31 17.49 270 top
R1302  10KR2F-L1-GP  [R402H15]  52.01 21.63 90 top
R1303  -  [0R0402-PAD]  50.29 21.63 270 top
R1305  2R2F-GP  [R402H16]  48.53 42.51 270 top
R1306  10KR2F-2-GP  [R402H16]  52.85 22.95 90 top
R1307  0R2J-L-GP  [R402H15]  51.07 22.95 270 top
R1309  24D9R2F-L-GP  [R402H16]  48.53 44.03 270 top
R1310  10KR2F-L1-GP  [R402H15]  45.51 44.49 180 top
R1311  -  [0R0402-PAD]  46.81 44.03 90 top
R1312  240R2F-1-GP  [R402H16]  48.36 53.96 270 top
R1501  100R2F-L1-GP-U  [R402H14]  135.78 40.98 270 bottom
R1502  200R2F-L-GP  [R402H16]  114.07 35.27 90 top
R1503  10KR2J-3-GP  [R402H16]  135.91 36.16 90 bottom
R1603  113R2F-GP  [R402H16]  120.03 37.16 90 top
R1604  100R2F-L1-GP-U  [R402H14]  127.02 37.3 90 top
R1606  10KR2J-3-GP  [R402H16]  123.97 24.73 0 bottom
R1607  10KR2J-3-GP  [R402H16]  113.48 42.71 0 top
R1608  10KR2J-3-GP  [R402H16]  123.21 24.73 0 bottom
R1609  -  [0R0402-PAD]  116.61 35.27 0 top
R1610  -  [0R0402-PAD]  115.84 35.27 0 top
R1701  10KR2J-3-GP  [R402H16]  116.86 38.82 45 top
R1702  1KR2J-1-GP  [R402H16]  89.81 16.47 270 top
R1704  -  [0R0402-PAD]  107.87 14.26 270 bottom
R1706  -  [0R0402-PAD]  107.87 15.03 90 bottom
R1707  10KR2J-3-GP  [R402H16]  73.3 19.39 90 top
R1708  -  [0R0402-PAD]  115.97 20.03 180 bottom
R1711  -  [0R0603-PAD]  73.3 17.49 270 top
R1713  -  [0R0402-PAD]  116.86 21.17 0 bottom
R1714  10KR2J-3-GP  [R402H16]  124.61 82.13 180 bottom
R1715  100KR2J-1-GP  [R402H16]  117.88 19.9 270 bottom
R1716  100KR2F-L1-GP  [R402H16]  122.45 83.78 270 bottom
R1717  10KR2J-3-GP  [R402H16]  138.09 35.37 270 bottom
R1719  47KR2F-GP  [R402H16]  123.72 84.16 0 bottom
R1720  -  [0R0402-PAD]  90.7 15.45 90 top
R1726  10KR2J-3-GP  [R402H16]  89.43 12.15 90 top
R1727  100KR2J-1-GP  [R402H16]  91.21 12.15 90 top
R1728  -  [0R0402-PAD]  92.1 13.8 90 top
R1730  330KR2J-L1-GP  [R402H16]  95.02 32.6 90 top
R1731  20KR2J-L2-GP  [R402H16]  115.89 40.45 270 top
R1737  100KR2J-1-GP  [R402H16]  86.76 14.57 270 top
R1738  10KR2J-3-GP  [R402H16]  115.21 20.03 0 bottom
R1802  1MR2J-1-GP  [R402H16]  136.06 55.71 180 bottom
R1803  2K7R2F-GP  [R402H16]  127.5 57.82 0 top
R1805  15R2F-2-GP  [R402H16]  94 34.76 270 top
R1809  0R2J-2-GP  [R402H16]  135.3 55.71 180 bottom
R1810  0R2J-2-GP  [R402H16]  135.3 53.94 0 bottom
R1811  10R2F-L-GP  [R402H14]  99.97 29.42 270 bottom
R1812  -  [0R0402-PAD]  99.97 28.66 270 bottom
R1813  -  [0R0402-PAD]  97.81 48.98 90 top
R1815  10MR2J-L-GP  [R402H16]  104.67 19.26 180 bottom
R1816  10KR2J-3-GP  [R402H16]  76.6 26.76 180 top
R1818  8K2R2F-1-GP  [R402H16]  114.45 20.03 180 bottom
R1820  10KR2J-3-GP  [R402H16]  97.89 36.13 90 top
R1822  1KR2J-1-GP  [R402H16]  117.24 22.82 90 bottom
R1823  1KR2J-1-GP  [R402H16]  115.46 22.82 90 bottom
R1824  1KR2J-1-GP  [R402H16]  98.34 30.34 180 top
R1825  1KR2J-1-GP  [R402H16]  97.89 32.32 270 top
R1827  15R2F-2-GP  [R402H16]  93.62 41.24 90 top
R1828  15R2F-2-GP  [R402H16]  93.62 42 90 top
R1829  15R2F-2-GP  [R402H16]  93.62 42.76 90 top
R1830  15R2F-2-GP  [R402H16]  93.62 43.52 90 top
R1836  2K2R2J-2-GP  [R402H16]  119.02 22.82 270 bottom
R1837  150KR2J-GP  [R402H16]  95.65 30.95 180 top
R1838  0R2J-2-GP  [R402H16]  99.97 27.9 270 bottom
R1901  200R2F-L-GP  [R402H16]  120.04 37.93 90 top
R1908  -  [0R0402-PAD]  97.81 45.68 90 top
R1909  1KR2J-1-GP  [R402H16]  96.84 48.12 90 top
R1910  1KR2J-1-GP  [R402H16]  96.03 36.92 0 top
R1911  10KR2J-3-GP  [R402H16]  147.21 27.65 90 top
R1912  10KR2J-3-GP  [R402H16]  150.13 28.31 270 top
R1913  10KR2J-3-GP  [R402H16]  97.89 35.37 90 top
R1914  10KR2J-3-GP  [R402H16]  97.89 33.84 90 top
R1915  10KR2J-3-GP  [R402H16]  98.22 35.17 0 bottom
R1916  10KR2J-3-GP  [R402H16]  97.89 34.61 90 top
R1917  10KR2J-3-GP  [R402H16]  98.98 36.64 0 bottom
R1918  10KR2J-3-GP  [R402H16]  100.5 35.11 0 bottom
R1919  10KR2J-3-GP  [R402H16]  97.89 33.08 90 top
R1920  10KR2J-3-GP  [R402H16]  99.74 36.64 0 bottom
R2001  10KR2F-2-GP  [R402H16]  92.48 30.69 90 top
R2002  10KR2J-3-GP  [R402H16]  90.83 33.11 0 top
R2003  -  [0R0402-PAD]  114.32 24.6 0 bottom
R2004  -  [0R0402-PAD]  113.56 24.47 0 bottom
R2007  1KR2J-1-GP  [R402H16]  115.97 17.36 0 bottom
R2009  10KR2J-3-GP  [R402H16]  117.67 29.88 270 bottom
R2010  10KR2J-3-GP  [R402H16]  118.08 28.61 0 bottom
R2019  1KR2J-1-GP  [R402H16]  116.73 17.36 180 bottom
R2020  -  [0R0402-PAD]  120.64 22.33 180 bottom
R2021  -  [0R0402-PAD]  121.51 22.33 180 bottom
R2023  -  [0R0402-PAD]  71.27 100.54 270 top
R2024  -  [0R0402-PAD]  72.94 100.54 90 top
R2025  0R2J-2-GP  [R402H16]  214.52 58.89 180 top
R2026  0R2J-2-GP  [R402H16]  217.93 56.45 180 top
R2027  0R2J-2-GP  [R402H16]  218.33 53.81 90 top
R2028  0R2J-2-GP  [R402H16]  74.7 100.54 90 top
R2029  10KR2J-3-GP  [R402H16]  114.83 29.42 0 bottom
R2030  10KR2J-3-GP  [R402H16]  114.07 29.42 180 bottom
R2031  10KR2J-3-GP  [R402H16]  71.27 101.31 90 top
R2032  10KR2J-3-GP  [R402H16]  72.94 101.31 270 top
R2033  10KR2J-3-GP  [R402H16]  217.34 57.82 270 top
R2034  10KR2J-3-GP  [R402H16]  216.68 55.97 90 top
R2035  10KR2J-3-GP  [R402H16]  219.1 53.05 270 top
R2036  10KR2J-3-GP  [R402H16]  74.32 101.81 0 top
R2037  10KR2J-3-GP  [R402H16]  122.45 32.35 90 top
R2038  10KR2J-3-GP  [R402H16]  121.18 32.45 180 top
R2039  0R2J-2-GP  [R402H16]  75.2 97.24 90 top
R2040  10KR2J-3-GP  [R402H16]  117.75 24.98 0 bottom
R2041  10KR2J-3-GP  [R402H16]  115.21 17.36 0 bottom
R2042  10KR2J-3-GP  [R402H16]  120.06 29.42 0 bottom
R2043  10KR2J-3-GP  [R402H16]  111.7 32.8 180 top
R2044  10KR2J-3-GP  [R402H16]  117.24 28.61 0 bottom
R2045  10KR2J-3-GP  [R402H16]  126.21 18.81 270 top
R2046  10KR2J-3-GP  [R402H16]  221.25 39.84 270 top
R2047  10KR2J-3-GP  [R402H16]  119.27 29.42 0 bottom
R2048  51KR2J-1-GP  [R402H16]  115.59 29.42 0 bottom
R2049  51KR2J-1-GP  [R402H16]  116.35 29.42 0 bottom
R2050  10KR2J-3-GP  [R402H16]  90.83 31.33 0 top
R2051  10KR2J-3-GP  [R402H16]  120.04 35.88 180 top
R2052  10KR2J-3-GP  [R402H16]  120.39 32.45 180 top
R2053  10KR2J-3-GP  [R402H16]  75.08 101.81 0 top
R2101  -  [0R0402-PAD]  116.71 46.42 180 top
R2106  -  [0R0603-PAD]  75.84 22.06 90 top
R2107  -  [0R0603-PAD]  124.99 36.92 90 top
R2108  -  [0R0603-PAD]  123.85 35.65 270 top
R2109  -  [0R0603-PAD]  138.45 38.95 180 bottom
R2110  -  [0R0603-PAD]  123.45 45.68 270 top
R2111  -  [0R0603-PAD]  139.72 38.95 180 bottom
R2201  1MR2J-1-GP  [R402H16]  139.21 29.68 0 bottom
R2202  0R2J-2-GP  [R402H16]  138.45 30.69 0 bottom
R2203  0R2J-2-GP  [R402H16]  138.45 28.92 180 bottom
R2402  -  [0R0402-PAD]  139.72 10.88 270 bottom
R2406  -  [0R0402-PAD]  162.07 25.11 90 top
R2407  100KR2J-1-GP  [R402H16]  162.07 25.87 90 top
R2408  0R2J-2-GP  [R402H16]  162.07 24.34 90 top
R2409  0R2J-2-GP  [R402H16]  154.07 26.38 0 top
R2414  4K7R2J-2-GP  [R402H16]  179.98 5.29 90 top
R2415  10KR2J-3-GP  [R402H16]  159.02 22.95 0 bottom
R2417  100KR2J-1-GP  [R402H16]  140.86 14.82 0 top
R2418  0R2J-2-GP  [R402H16]  139.59 15.33 270 top
R2421  330R2J-3-GP  [R402H16]  148.48 5.68 270 top
R2424  20KR2F-L-GP  [R402H16]  162.96 21.55 180 top
R2426  10KR2J-3-GP  [R402H16]  161.82 18.76 270 top
R2427  0R2J-2-GP  [R402H16]  138.96 20.41 180 top
R2428  -  [0R0402-PAD]  160.8 24.73 180 top
R2429  10KR2J-3-GP  [R402H16]  135.91 35.39 270 bottom
R2430  10KR2J-3-GP  [R402H16]  155.98 25.87 0 top
R2432  1KR2J-1-GP  [R402H16]  160.93 4.91 270 top
R2434  100KR2J-1-GP  [R402H16]  161.82 12.41 270 top
R2435  -  [0R0402-PAD]  140.74 22.31 270 top
R2436  100KR2J-1-GP  [R402H16]  140.23 20.79 90 top
R2437  43R2J-GP  [R402H16]  145.05 3.26 0 top
R2439  0R2J-2-GP  [R402H16]  144.17 25.36 90 top
R2441  100KR2F-L1-GP  [R402H16]  146.45 2.5 90 top
R2442  154KR2F-GP  [R402H16]  146.45 1.74 270 top
R2443  49K9R2F-L-GP  [R402H16]  151.02 4.53 0 top
R2444  100KR2F-L1-GP  [R402H16]  149.12 2.12 180 top
R2445  -  [0R0402-PAD]  148.36 2.12 180 top
R2446  -  [0R0603-PAD]  149.88 16.47 90 bottom
R2447  -  [0R0402-PAD]  161.82 10.88 90 top
R2448  10KR2F-2-GP  [R402H16]  162.2 21.55 180 top
R2449  100KR2J-1-GP  [R402H16]  140.74 21.55 90 top
R2450  100KR2J-1-GP  [R402H16]  148.23 17.61 0 bottom
R2451  100KR2J-1-GP  [R402H16]  160.93 4.15 90 top
R2454  100KR2J-1-GP  [R402H16]  153.97 4.66 0 top
R2458  10KR2J-3-GP  [R402H16]  153.18 26.38 180 top
R2459  -  [0R0402-PAD]  161.82 11.64 90 top
R2461  0R2J-2-GP  [R402H16]  159.53 2.75 180 top
R2462  -  [0R0402-PAD]  149.25 26.38 180 top
R2463  1KR2J-1-GP  [R402H16]  154.73 4.66 0 top
R2464  10KR2J-3-GP  [R402H16]  147.21 26 90 top
R2470  -  [0R0402-PAD]  163.85 15.2 180 top
R2471  0R2J-2-GP  [R402H16]  163.34 19.39 180 top
R2472  -  [0R0402-PAD]  162.2 3.77 0 top
R2473  10KR2J-3-GP  [R402H16]  151.79 7.33 90 bottom
R2475  0R2J-2-GP  [R402H16]  18.94 78.32 90 top
R2477  -  [0R0402-PAD]  161.82 10.12 270 top
R2478  -  [0R0402-PAD]  139.34 12.15 90 top
R2479  0R2J-2-GP  [R402H16]  162.07 23.58 270 top
R2480  100KR2J-1-GP  [R402H16]  179.98 4.53 90 top
R2481  150KR2F-L-GP  [R402H16]  149.5 4.79 90 top
R2482  115KR2F-GP  [R402H16]  150.39 3.26 270 top
R2483  330R2J-3-GP  [R402H16]  148.74 6.18 180 bottom
R2484  100KR2J-1-GP  [R402H16]  157.37 8.98 90 bottom
R2489  100KR2J-1-GP  [R402H16]  139.59 22.19 180 bottom
R2490  -  [0R0402-PAD]  164.1 19.39 180 top
R2494  0R2J-2-GP  [R402H16]  151.15 1.74 270 top
R2496  100KR2J-1-GP  [R402H16]  159.53 4.53 0 top
R2499  0R2J-2-GP  [R402H16]  18.94 77.56 90 top
R2501  4K7R2J-2-GP  [R402H16]  158.39 16.98 90 bottom
R2503  10R2F-L-GP  [R402H14]  171.85 17.11 270 bottom
R2504  10MR2J-L-GP  [R402H16]  170.71 4.91 0 top
R2505  1K6R2F-GP  [R402H16]  175.28 3.26 270 top
R2515  -  [0R0402-PAD]  170.71 12.03 270 bottom
R2517  47KR2F-GP  [R402H16]  175.28 2.5 90 top
R2601  0R2J-2-GP  [R402H16]  45.36 13.04 0 top
R2602  -  [0R0402-PAD]  148.48 14.95 0 bottom
R2603  7K5R2F-1-GP  [R402H16]  54.5 13.55 270 top
R2604  7K5R2F-1-GP  [R402H16]  46.12 13.04 180 top
R2607  10KR2J-3-GP  [R402H16]  149.75 15.33 90 bottom
R2608  27KR2F-L-GP  [R402H16]  141.12 74.76 180 top
R2609  10R2F-L-GP  [R402H14]  141.88 74.76 180 top
R2610  NTC-100K-8-GP  [NTC-603H38]  143.02 76.03 180 top
R2611  -  [0R0402-PAD]  140.99 76.54 0 top
R2612  -  [0R0402-PAD]  205.89 71.97 180 top
R2613  -  [0R0402-PAD]  208.55 72.48 0 top
R2614  -  [0R0402-PAD]  207.79 72.48 0 top
R2615  0R2J-2-GP  [R402H16]  147.72 14.95 0 bottom
R2616  0R2J-2-GP  [R402H16]  45.49 7.71 180 top
R2617  -  [0R0402-PAD]  44.72 7.71 180 top
R2705  -  [0R0603-PAD]  22.96 9.45 0 top
R2707  -  [0R0805-PAD]  24.07 6.44 90 bottom
R2712  -  [0R0805-PAD]  24.07 8.24 90 bottom
R2721  -  [0R0402-PAD]  29.26 17.06 270 top
R2724  -  [0R0603-PAD]  24.53 23.2 0 top
R2726  10KR2J-3-GP  [R402H16]  21.61 30.69 270 top
R2727  20KR2J-L2-GP  [R402H16]  21.48 32.6 90 top
R2729  -  [0R0402-PAD]  18.36 12.84 90 top
R2730  -  [0R0402-PAD]  28.02 20.84 0 top
R2737  -  [0R0402-PAD]  29.74 13.8 270 top
R2738  -  [0R0402-PAD]  29.33 16.19 270 top
R2739  -  [0R0805-PAD]  17.52 22.57 180 top
R2740  -  [0R0402-PAD]  27.26 20.84 0 top
R2741  200KR2F-L-GP  [R402H16]  28.6 12.66 180 bottom
R2742  100KR2J-1-GP  [R402H16]  27.83 14.06 90 bottom
R2743  10KR2J-3-GP  [R402H16]  29.87 13.42 90 bottom
R2744  100KR2J-1-GP  [R402H16]  29.87 12.66 90 bottom
R2745  2K2R2J-2-GP  [R402H16]  13.23 15.45 270 top
R2746  0R2J-2-GP  [R402H16]  29.74 19.52 270 top
R2747  100KR2J-1-GP  [R402H16]  22.22 9.71 0 bottom
R2748  0R3J-0-U-GP  [R603H22]  33.29 14.77 270 top
R2749  -  [0R0603-PAD]  33.29 16.06 90 top
R2750  0R3J-0-U-GP  [R603H22]  19.2 22.44 180 bottom
R2751  -  [0R0603-PAD]  20.52 22.74 0 bottom
R2752  -  [0R0402-PAD]  29.74 20.28 270 top
R2753  -  [0R0402-PAD]  18.36 14.39 90 top
R2754  0R2J-2-GP  [R402H16]  18.36 13.63 90 top
R2905  -  [0R0402-PAD]  14.42 13.09 90 bottom
R2906  -  [0R0603-PAD]  19.07 13.5 0 bottom
R2907  -  [0R0603-PAD]  18.08 17.92 90 top
R2908  10R2F-L-GP  [R402H14]  16.41 12.91 180 bottom
R2909  -  [0R0603-PAD]  18.08 19.19 90 top
R2910  10R2F-L-GP  [R402H14]  14.96 8.98 315 bottom
R2911  -  [0R0603-PAD]  17.8 15.45 0 bottom
R2912  -  [0R0402-PAD]  35.07 3.77 270 top
R2913  -  [0R0402-PAD]  35.58 5.55 0 top
R2914  -  [0R0402-PAD]  30.25 10.63 0 top
R2915  -  [0R0402-PAD]  32.66 9.49 0 top
R2921  -  [0R0402-PAD]  14.45 11.9 90 bottom
R2922  -  [0R0402-PAD]  15.51 16.09 90 top
R2923  -  [0R0603-PAD]  11.53 14.39 90 top
R3401  -  [0R0402-PAD]  17.29 42.12 270 bottom
R3402  -  [0R0402-PAD]  17.17 46.19 270 bottom
R3403  20KR2F-L-GP  [R402H16]  21.36 42.89 90 top
R3404  22K1R2F-L-GP  [R402H16]  21.36 42.12 90 top
R3405  -  [0R0402-PAD]  17.29 40.98 270 bottom
R3406  -  [0R0402-PAD]  17.29 44.28 270 bottom
R3501  100KR2J-1-GP  [R402H16]  14.75 39.2 90 bottom
R3605  -  [0R0402-PAD]  20.09 50.51 270 top
R3606  -  [0R0402-PAD]  20.09 51.27 270 top
R3609  -  [0R0402-PAD]  20.09 48.98 270 top
R3610  -  [0R0402-PAD]  20.09 49.74 270 top
R3611  -  [0R0402-PAD]  22.73 27.62 270 top
R3612  -  [0R0402-PAD]  22.75 25.51 270 top
R3613  -  [0R0402-PAD]  22.75 26.28 270 top
R3614  -  [0R0402-PAD]  22.73 28.38 270 top
R3706  1MR2J-1-GP  [R402H16]  29.48 25.61 90 top
R3707  2K2R2J-2-GP  [R402H16]  29.48 28.66 90 top
R3708  30KR2J-4-GP  [R402H16]  33.8 23.07 180 top
R3709  10KR2F-2-GP  [R402H16]  34.56 23.33 0 top
R3724  4K7R2J-2-GP  [R402H16]  29.48 32.47 90 top
R3725  10KR2F-2-GP  [R402H16]  28.21 26.76 0 top
R3726  10KR2F-2-GP  [R402H16]  29.48 30.95 90 top
R3727  -  [0R0402-PAD]  35.07 34.38 180 top
R3728  -  [0R0402-PAD]  33.04 34.38 180 top
R3729  -  [0R0402-PAD]  29.48 26.38 270 top
R3730  100KR2F-L1-GP  [R402H16]  29.48 31.71 90 top
R3731  -  [0R0402-PAD]  29.48 29.42 90 top
R3732  -  [0R0603-PAD]  39.01 22.44 270 top
R3733  -  [0R0402-PAD]  40.66 23.2 180 top
R3734  100KR2F-L1-GP  [R402H16]  29.1 34.5 0 top
R3735  2MR2-GP  [R402H16]  30.88 25.61 0 top
R3736  -  [0R0603-PAD]  34.06 34.63 0 top
R3738  10KR2J-3-GP  [R402H16]  41.8 29.93 0 top
R3739  909KR2F-GP  [R402H16]  37.43 34.3 180 top
R3740  301KR2F-1-GP  [R402H16]  38.63 36.16 90 top
R3741  30KR2F-GP  [R402H16]  35.33 22.95 0 top
R3742  10KR2F-L1-GP  [R402H15]  36.09 22.95 180 top
R3801  10KR2J-L-GP  [R402H15]  36.22 63.21 90 top
R3802  10KR2J-L-GP  [R402H15]  37.99 63.21 270 top
R3812  -  [0R0603-PAD]  32.15 48.86 180 top
R3814  -  [0R0402-PAD]  40.79 61.68 270 top
R3816  -  [0R0402-PAD]  40.79 62.44 270 top
R3818  10KR2J-3-GP  [R402H16]  32.79 60.16 90 top
R3821  4K7R2J-2-GP  [R402H16]  32.79 58.76 90 top
R3830  2MR2F-GP  [R402H16]  16.15 99.53 90 top
R3831  2MR2F-GP  [R402H16]  16.15 100.29 90 top
R3832  -  [0R0402-PAD]  9.67 90.77 0 bottom
R3833  -  [0R0402-PAD]  10.43 90.77 0 bottom
R3834  -  [0R0402-PAD]  14.12 88.1 180 top
R3835  -  [0R0402-PAD]  14.88 88.1 180 top
R3836  -  [0R0402-PAD]  12.34 90.77 0 bottom
R3837  -  [0R0402-PAD]  11.58 90.77 0 bottom
R3838  -  [0R0402-PAD]  16.66 88.48 180 top
R3839  -  [0R0402-PAD]  15.9 88.48 180 top
R3840  1KR2J-1-GP  [R402H16]  33.04 56.48 90 top
R3841  1KR2J-1-GP  [R402H16]  32.91 57.24 270 top
R3842  1KR2J-1-GP  [R402H16]  32.79 54.32 90 top
R3843  1KR2J-1-GP  [R402H16]  33.17 55.08 270 top
R3844  20KR2J-L3-GP  [R402H16]  34.44 50.38 0 top
R3845  1KR2J-1-GP  [R402H16]  42.18 52.54 180 top
R3846  1KR2J-1-GP  [R402H16]  41.42 52.54 0 top
R3847  1KR2J-1-GP  [R402H16]  32.91 51.14 180 top
R3849  -  [0R0402-PAD]  39.77 63.71 270 top
R3852  1KR2J-1-GP  [R402H16]  35.2 50.38 180 top
R3853  -  [0R0402-PAD]  37.61 40.85 270 top
R3854  -  [0R0402-PAD]  35.07 39.97 90 top
R3855  -  [0R0402-PAD]  34.06 46.7 0 top
R3856  -  [0R0402-PAD]  35.58 46.7 0 top
R3857  -  [0R0402-PAD]  33.29 46.7 0 top
R3858  -  [0R0402-PAD]  36.34 46.7 0 top
R3859  -  [0R0402-PAD]  29.99 44.92 180 top
R3860  -  [0R0402-PAD]  39.39 44.28 90 top
R3861  0R2J-2-GP  [R402H16]  11.58 91.27 270 top
R3862  0R2J-2-GP  [R402H16]  11.58 92.04 270 top
R3863  0R2J-2-GP  [R402H16]  11.58 93.69 270 top
R3864  0R2J-2-GP  [R402H16]  11.58 92.92 270 top
R3870  1KR2J-1-GP  [R402H16]  33.68 51.14 0 top
R3871  1KR2J-1-GP  [R402H16]  42.44 56.09 270 top
R3872  1KR2J-1-GP  [R402H16]  45.99 56.35 180 top
R3873  1KR2J-1-GP  [R402H16]  45.08 58.71 0 top
R3874  1KR2J-1-GP  [R402H16]  42.84 59.52 270 top
R4002  -  [0R0402-PAD]  155.21 19.39 180 bottom
R4003  10KR2J-3-GP  [R402H16]  81.78 6.34 180 top
R4005  1KR2J-1-GP  [R402H16]  150.64 22.57 270 bottom
R4006  20KR2F-L-GP  [R402H16]  164.23 6.56 270 top
R4009  10KR2J-3-GP  [R402H16]  165.5 6.95 180 top
R4010  0R2J-2-GP  [R402H16]  198.78 47.84 270 top
R4011  -  [0R0402-PAD]  154.45 19.39 0 bottom
R4017  0R2J-2-GP  [R402H16]  81 6.16 180 top
R4024  -  [0R0402-PAD]  109.49 12.53 270 bottom
R4029  -  [0R0402-PAD]  151.15 19.39 0 bottom
R4030  -  [0R0402-PAD]  151.91 19.39 0 bottom
R4031  100KR2J-1-GP  [R402H16]  150.13 17.49 90 bottom
R4032  100KR2J-1-GP  [R402H16]  148.99 18.88 270 bottom
R4033  0R2J-2-GP  [R402H16]  152.67 19.39 0 bottom
R4036  -  [0R0402-PAD]  114.32 10.88 270 bottom
R4037  0R2J-2-GP  [R402H16]  78.23 7.43 0 top
R4038  -  [0R0402-PAD]  114.32 10.12 270 bottom
R4042  -  [0R0402-PAD]  136.16 61.05 270 bottom
R4045  -  [0R1206-PAD]  73.93 11.14 180 top
R4101  -  [0R0805-PAD]  114.7 14.06 0 bottom
R4301  -  [0R0402-PAD]  188.23 20.15 270 top
R4303  1KR2F-3-GP  [R402H16]  12.97 85.18 180 bottom
R4304  1MR2J-1-GP  [R402H16]  32.99 75.4 90 top
R4305  0R2J-2-GP  [R402H16]  33.4 73.87 270 top
R4306  0R2J-2-GP  [R402H16]  44.09 45.55 270 top
R5501  -  [0R0402-PAD]  112.03 96.86 270 top
R5502  0R2J-2-GP  [R402H16]  88.16 93.18 0 bottom
R5503  -  [0R0402-PAD]  90.32 93.81 90 bottom
R5504  100KR2J-1-GP  [R402H16]  74.32 96.48 270 top
R5506  100R2J-2-GP  [R402H14]  95.04 89.14 180 bottom
R5507  -  [0R0603-PAD]  68.09 93.18 90 top
R5517  4K7R2J-2-GP  [R402H16]  78.76 100.54 0 top
R5518  4K7R2J-2-GP  [R402H16]  78 100.54 0 top
R5520  -  [0R0603-PAD]  116.99 101.18 90 top
R5521  -  [0R0402-PAD]  79.52 100.54 180 top
R5522  -  [0R0402-PAD]  77.24 100.54 180 top
R5523  -  [0R0402-PAD]  77.62 97.12 0 top
R5526  0R3J-0-U-GP  [R603H22]  68.09 94.45 90 top
R5527  -  [0R0603-PAD]  73.81 93.05 270 bottom
R5528  -  [0R0603-PAD]  67.46 99.66 90 top
R5540  -  [0R0402-PAD]  107.94 98.77 270 top
R5541  31K6R2F-GP  [R402H16]  70.28 93.79 0 bottom
R5542  10KR2F-2-GP  [R402H16]  68.85 95.34 90 bottom
R5543  -  [0R0402-PAD]  75.97 99.53 270 top
R5544  -  [0R0402-PAD]  76.73 94.58 270 top
R5545  100KR2J-1-GP  [R402H16]  76.35 95.97 90 top
R5701  5D1R2F-GP  [R402H16]  17.42 67.4 270 top
R5702  5D1R2F-GP  [R402H16]  17.42 68.16 270 top
R5703  5D1R2F-GP  [R402H16]  17.42 69.18 270 top
R5704  5D1R2F-GP  [R402H16]  17.42 69.94 270 top
R5705  5D1R2F-GP  [R402H16]  17.29 70.95 270 top
R5706  5D1R2F-GP  [R402H16]  17.29 71.72 270 top
R5707  5D1R2F-GP  [R402H16]  17.17 72.71 270 top
R5708  5D1R2F-GP  [R402H16]  17.17 73.47 270 top
R5710  -  [0R0402-PAD]  19.32 67.4 270 top
R5711  -  [0R0402-PAD]  19.32 68.16 270 top
R5712  -  [0R0402-PAD]  19.32 69.94 270 top
R5713  -  [0R0402-PAD]  19.32 69.18 270 top
R5714  -  [0R0402-PAD]  19.2 71.72 270 top
R5715  -  [0R0402-PAD]  19.2 70.95 270 top
R5716  -  [0R0402-PAD]  18.92 73.47 270 top
R5717  -  [0R0402-PAD]  18.92 72.71 270 top
R5734  4D3KR2F-GP  [R402H16]  22.5 62.44 270 top
R5735  4K7R2J-2-GP  [R402H16]  20.09 74.51 270 bottom
R5736  10KR2J-3-GP  [R402H16]  19.83 81.88 270 bottom
R5737  10KR2J-3-GP  [R402H16]  23.26 61.68 90 top
R5738  4K7R2J-2-GP  [R402H16]  16.91 66.51 90 top
R5739  4K7R2J-2-GP  [R402H16]  16.91 65.75 90 top
R5740  4K7R2J-2-GP  [R402H16]  17.17 75.3 90 bottom
R5741  10KR2J-3-GP  [R402H16]  18.41 74.54 90 bottom
R5742  4K7R2J-2-GP  [R402H16]  21.76 77.79 180 bottom
R5743  4K7R2J-2-GP  [R402H16]  20.11 75.3 270 bottom
R5748  470R2F-GP  [R402H16]  20.47 64.73 180 top
R5750  1MR2J-L3-GP  [R402H16]  21.23 64.73 180 top
R5751  2K2R2J-2-GP  [R402H16]  14.22 74.13 0 bottom
R5754  4K7R2J-2-GP  [R402H16]  20.09 73.75 270 bottom
R5755  2K2R2J-2-GP  [R402H16]  14.98 74.13 0 bottom
R5756  4K7R2J-2-GP  [R402H16]  20.47 62.06 180 top
R5757  4K7R2J-2-GP  [R402H16]  21.23 62.06 180 top
R5758  100KR2J-1-GP  [R402H16]  14.75 74.64 270 top
R5760  1KR2F-3-GP  [R402H16]  25.8 75.78 0 top
R5761  0R2J-2-GP  [R402H16]  18.69 74.38 270 top
R5762  68R2F-GP  [R402H16]  40.66 67.52 180 top
R5763  68R2F-GP  [R402H16]  40.66 65.75 0 top
R5801  0R0402-PAD-1-GP  [0R0402-PAD]  21.74 55.21 0 bottom
R5802  5K1R2F-2-GP  [R402H16]  19.32 63.84 270 bottom
R5803  10KR2F-2-GP  [R402H16]  21.33 63.97 270 bottom
R6001  -  [0R0402-PAD]  218.71 5.8 0 top
R6002  -  [0R0402-PAD]  224.81 5.55 0 top
R6006  -  [0R0603-PAD]  229.38 6.31 0 top
R6120  10KR2J-3-GP  [R402H16]  50.44 3.77 180 top
R6301  -  [0R0402-PAD]  229.38 18.12 270 top
R6302  -  [0R0603-PAD]  229.64 26.25 0 top
R6303  10KR2J-3-GP  [R402H16]  229.38 17.36 90 top
R6304  10KR2J-3-GP  [R402H16]  229.38 16.6 270 top
R6305  100KR2F-L1-GP  [R402H16]  212.36 13.3 90 bottom
R6307  -  [0R0603-PAD]  228.37 26.25 0 top
R6308  -  [0R0402-PAD]  229.38 15.84 270 top
R6401  499R2F-2-GP  [R402H16]  56.6 6.44 0 top
R6402  330R2J-3-GP  [R402H16]  55.71 6.44 0 top
R6403  -  [0R0402-PAD]  47.9 3.9 0 top
R6404  -  [0R0402-PAD]  50.57 6.06 270 top
R6502  0R3J-0-U-GP  [R603H22]  126.13 17.23 90 bottom
R6503  100R3J-4-GP  [R603H22]  123.08 13.8 90 bottom
R6504  20KR2F-L-GP  [R402H16]  116.99 13.93 90 bottom
R6505  0R2J-2-GP  [R402H16]  125.24 18.76 0 bottom
R6506  0R2J-2-GP  [R402H16]  121.94 19.34 180 bottom
R6507  51KR2J-1-GP  [R402H16]  94.64 15.71 180 bottom
R6508  100KR2J-1-GP  [R402H16]  95.91 16.09 270 bottom
R6509  100KR2J-1-GP  [R402H16]  90.32 15.84 0 bottom
R6510  -  [0R0402-PAD]  98.42 17.13 0 bottom
R6511  10KR2J-3-GP  [R402H16]  130.45 9.99 180 bottom
R6512  -  [0R0402-PAD]  144.42 23.2 270 bottom
R6513  1KR2J-1-GP  [R402H16]  147.98 26 270 bottom
R6514  -  [0R0603-PAD]  126.51 15.2 0 bottom
R6601  0R3J-0-U-GP  [R603H22]  205.25 55.08 0 top
R6602  0R3J-0-U-GP  [R603H22]  205.25 52.67 0 top
R6604  100KR2J-1-GP  [R402H16]  216.94 47.46 0 top
R6605  -  [0R0402-PAD]  207.41 49.49 90 top
R6606  -  [0R0402-PAD]  207.41 48.73 90 top
